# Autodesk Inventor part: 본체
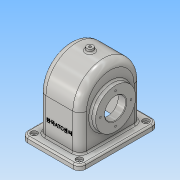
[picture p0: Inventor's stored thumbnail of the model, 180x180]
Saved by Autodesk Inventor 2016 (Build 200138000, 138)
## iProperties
Created: 2018-08
Part Number: 본체
Material: 알루미늄 6061
Document SubType Name: Modeling
Designer: Administrator
Density: 2.7 g/cm^3
Appearance: 알루미늄 - 평지
Mass: 1092.08 g
Surface Area: 1182.21 cm^2
Volume: 404.475 cm^3
Author: Administrator
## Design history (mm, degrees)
sketch "스케치1"
  geometry: L1 (-55, -75)-(55, -75); L2 (55, -75)-(55, 75); L3 (55, 75)-(-55, 75); L4 (-55, 75)-(-55, -75); L5 (-55, -75)-(55, 75); L6 (55, -75)-(-55, 75); 1 further point
  constraints: 12 end point, 2 midpoint, 2 parallel, 1 horizontal, 1 perpendicular
  dimensions: "d0" = 110 distance of L3.end L2.end; "d1" = 150 distance of L2.end L1.end
extrude "돌출1" new body sketch "스케치1" distance "d2" = 10; taper "d3" = 0 deg
sketch "스케치2"
  geometry: L1 (0, 0)-(0, 149.117); L2 (-138.958, 78)-(166.911, 78); L3 (75, 0)-(-75, 0) reference; L4 (-58, 78)-(-58, 10); L5 (75, 10)-(-75, 10) reference; L6 (-58, 10)-(58, 10); L7 (-58, 78)-(58, 78); L8 (58, 78)-(58, 10); A1 r 58 centre (0, 78) between (58, 78) and (-58, 78)
  constraints: 12 end point, 5 point on line, 2 collinear, 2 point on circle, 2 vertical, 1 centre point, 1 horizontal, 1 perpendicular
  dimensions: "d4" = 78 distance between parallel lines of L3 L2; "d5" = 58 radius of A1
extrude "돌출2" join sketch "스케치2" stored distance "d6" = 77; taper "d7" = 0 deg
feature "쉘1" dims "d8" = 6, "d9" = 5, "d10" = 5
sketch "스케치3"
  geometry: L1 (33.5, -52)-(33.5, 52) reference; L2 (-33.5, -52)-(33.5, -52) reference; L3 (-33.5, 52)-(-33.5, -52) reference; L4 (33.5, 52)-(-33.5, 52) reference; L5 (50, -70)-(-50, -70) reference; L6 (50, 70)-(50, -70) reference; L7 (-50, 70)-(50, 70) reference; L8 (-50, -70)-(-50, 70) reference; 1 further point
extrude "돌출3" join sketch "스케치3" stored distance "d11" = 77; taper "d12" = 0 deg
sketch "스케치4" dims "d27" = 55
  geometry: L1 (86.979, 65)-(-81.045, 65); L2 (-55, 0)-(55, 0) reference; L3 (0, 0)-(0, 176.457); L4 (38.5, 103)-(43.5, 103); L5 (19.5, 93)-(33.5, 104.747); L6 (33.5, 78)-(33.5, 130) reference; L7 (38.5, 78)-(38.5, 136) reference; L8 (19.5, 93)-(19.5, 65); L9 (43.5, 103)-(43.5, 65); L10 (43.5, 65)-(19.5, 65); L11 (38.5, 103)-(33.5, 104.747); L12 (-33.5, 103)-(-48.5, 103); L13 (-48.5, 103)-(-48.5, 65); L14 (-33.5, 103)-(-33.5, 65); L15 (-33.5, 0)-(-33.5, 78) reference; L16 (-33.5, 65)-(-48.5, 65)
  constraints: 24 end point, 7 point on line, 4 horizontal, 3 perpendicular, 1 collinear, 1 vertical
  dimensions: "d13" = 65 distance between parallel lines of L2 L1; "d14" = 5 distance of L4.start L4.end; "d15" = 76 diameter of L4 L1; "d16" = 56 diameter of L5.start L1; "d17" = 50 deg angle of L8 L5; "d18" = 24 distance between parallel lines of L8 L9; "d20" = 76 diameter of L12 L1; "d21" = 87 distance from line of L7 L12.end; "d22" = 15 distance of L12.start L12.end
revolve "회전1" sketch "스케치4" stored, may be unused: angle "d19" = 90 deg
sketch "스케치5"
  geometry: L1 (53.528, 65)-(-63.279, 65); L2 (-55, 0)-(55, 0) reference; L3 (0, 0)-(0, 118.097); L4 (43.5, 27)-(43.5, 103) reference; L5 (43.5, 85)-(-48.5, 85); L6 (-48.5, 27)-(-48.5, 103) reference; L7 (43.5, 85)-(43.5, 65); L8 (-48.5, 85)-(-48.5, 65); L9 (-48.5, 65)-(43.5, 65)
  constraints: 12 end point, 2 horizontal, 2 midpoint, 2 point on line, 1 collinear, 1 vertical
  dimensions: "d23" = 65 distance between parallel lines of L2 L1; "d24" = 40 diameter of L5 L1
revolve "회전2" sketch "스케치5" stored, may be unused: angle "d25" = 90 deg
node "작업 평면1"
sketch "스케치6"
  geometry: L1 (0, 93.663)-(0, -103.553); L2 (55, 75)-(55, -75) reference; C1 r 6 at (0, 0); 1 further point
  constraints: 2 end point, 1 centre point, 1 coincident, 1 vertical
  dimensions: "d27" = 55 distance between parallel lines of L1 L2; "d28" = 12 diameter of C1
extrude "돌출4" join sketch "스케치6" stored distance "d29" = 77; taper "d30" = 5 deg
hole "구멍1" diameter "d33" = 4.459; stored, may be unused: countersink angle "d37" = 90 deg, drill point angle "d39" = 118 deg; dims "d31" = 10, "d32" = 10, "d34" = 10, "d35" = 4, "d36" = 2, "d38" = 12.8
sketch "스케치7" dims "d40" = 58
  geometry: L1 (0, 0)-(92.469, 0); C1 r 20 at (0, 0) reference; 2 further points
  constraints: 2 end point, 1 coincident, 1 horizontal, 1 horizontal alignment, 1 point on line, 2 other
hole "구멍2" sketch "스케치7" at (29, 0) diameter "d41" = 3.242; stored, may be unused: countersink angle "d45" = 90 deg, drill point angle "d47" = 118 deg; dims "d42" = 8, "d43" = 4, "d44" = 2, "d46" = 10
sketch "스케치9" dims "d51" = 58
  geometry: L1 (0, 0)-(-104.668, 0); C1 r 20 at (0, 0) reference; 3 further points
  constraints: 2 end point, 1 coincident, 1 horizontal, 1 horizontal alignment, 1 point on line, 2 other
hole "구멍3" sketch "스케치9" at (-29, 0) diameter "d52" = 3.242; stored, may be unused: countersink angle "d56" = 90 deg, drill point angle "d58" = 118 deg; dims "d53" = 8, "d54" = 4, "d55" = 2, "d57" = 10
fillet "모깎기1" dims "d62" = 12
fillet "모깎기2" dims "d63" = 13
fillet "모깎기3" dims "d64" = 3
hole "구멍4" diameter "d67" = 5; stored, may be unused: countersink angle "d71" = 90 deg, drill point angle "d73" = 118 deg; dims "d65" = 10, "d66" = 10, "d68" = 8, "d69" = 12, "d70" = 4, "d72" = 10
sketch "스케치11"
  geometry: L1 (-17.5, -78)-(-29.5, -78) reference; L2 (-13, 0)-(-13, -65) reference; 2 further points
  constraints: 1 other
  dimensions: "d74" = 40 distance from line of L1 point (25.5, -38); "d75" = 38.5 distance from line of L2 point (25.5, -38)
feature "엠보싱1" sketch "스케치11" dims "d0" = 110, "d1" = 150, "d76" = 0.5, "d77" = 0
fillet "모깎기4" dims "d78" = 8
chamfer "모따기1" distance "d79" = 1; stored, may be unused: second distance "d80" = 2, angle "d81" = 45 deg
fillet "모깎기5" dims "d82" = 3
sketch "스케치12"
  geometry: L1 (74.811, 151.447)-(-76.138, 151.447); L2 (-76.138, 151.447)-(-76.138, -13.768); L3 (-76.138, -13.768)-(74.811, -13.768); L4 (74.811, -13.768)-(74.811, 151.447); 1 further point
  constraints: 8 end point, 2 parallel, 1 horizontal, 1 perpendicular
extrude "돌출5" cut sketch "스케치12" stored distance "d83" = 77; taper "d84" = 0 deg
node "솔리드1"
pattern_circular "원형 패턴1" dims angle "d49" = 360 deg
pattern_circular "원형 패턴2" dims angle "d60" = 360 deg
mirror "대칭2"
mirror "대칭3"
node "투영된 루프1"
other parameters: "d26" = -142
